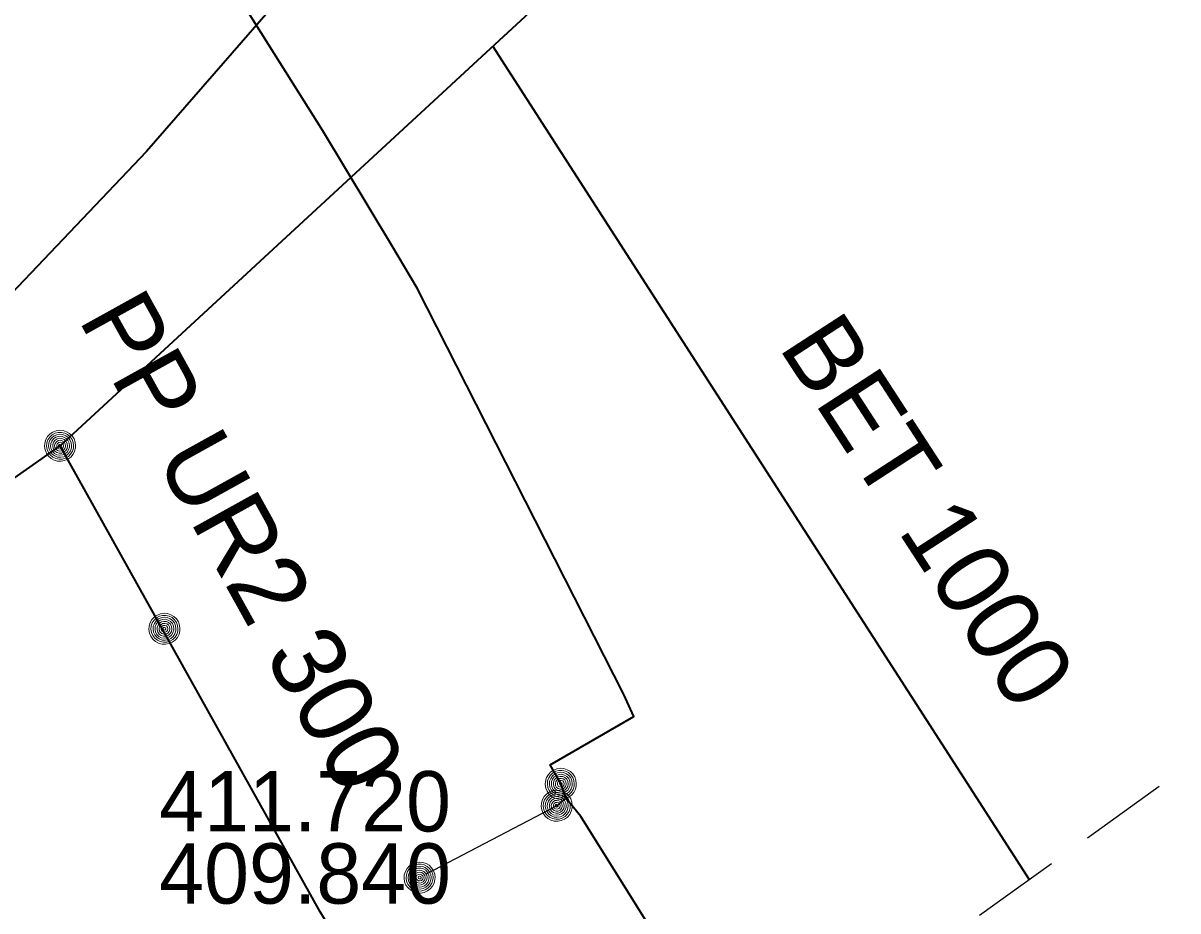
# Model space of a CAD drawing. Extents: x -867104 to -866746, y -1014489 to -1014255.
# Drawn here: x -866882.96 to -866865.74, y -1014478.06 to -1014464.82 of the extents above; entities that cross this region are included whole.
import ezdxf

# ---------------------------------------------------------------- set-up
doc = ezdxf.new("R2010")
doc.units = 0
doc.header["$LTSCALE"] = 0.44
doc.linetypes.add('DOT_DASHED', pattern=[7.7, 5, -1.2, 0.3, -1.2])
doc.linetypes.add('MEDIUM_DASHED', pattern=[4.5, 3, -1.5])
for name, color, linetype, lineweight in [('1', 7, 'Continuous', 35), ('12', 7, 'Continuous', 13), ('21', 7, 'Continuous', 35), ('25', 7, 'Continuous', 13), ('32', 7, 'Continuous', 13), ('62', 7, 'MEDIUM_DASHED', 25), ('8', 7, 'Continuous', 13)]:
    doc.layers.add(name, color=color, linetype=linetype, lineweight=lineweight)

msp = doc.modelspace()

# ---------------------------------------------------------------- linework, layer by layer
at = {"layer": '1'}
for points in [[(-866840.01, -1014396.11), (-866844.69, -1014400.78), (-866847.06, -1014402.96), (-866848.88, -1014406.15), (-866860.28, -1014424.67), (-866871.77, -1014440.29), (-866875.11, -1014444.27), (-866876.93, -1014446.09), (-866879, -1014449.37), (-866879.17, -1014450.73), (-866879.17, -1014451.68), (-866879.03, -1014452.53), (-866876.52, -1014455.41), (-866874.72, -1014458.69), (-866874.8, -1014459.33), (-866875.66, -1014460.47), (-866876.85, -1014461.77), (-866877.992, -1014463.135), (-866881.12, -1014466.73), (-866885.53, -1014471.37), (-866892.467, -1014476.423)], [(-866872.103, -1014480.579), (-866873.16, -1014479.02), (-866874.64, -1014476.65), (-866874.86, -1014476.38), (-866874.94, -1014476.16), (-866875.02, -1014476.02), (-866875.1, -1014475.88), (-866873.85, -1014475.16), (-866874, -1014474.83), (-866877.08, -1014468.77), (-866877.461, -1014468.135), (-866878.488, -1014466.421), (-866879.853, -1014464.243)]]:
    msp.add_lwpolyline(points, dxfattribs=at)
at = {"layer": '1', "linetype": 'DOT_DASHED', "lineweight": 25}
msp.add_lwpolyline([(-866874.86, -1014476.38), (-866875, -1014476.49), (-866877.045, -1014477.561)], dxfattribs=at)
at = {"layer": '12'}
for points in [[(-866874.708, -1014476.162), (-866874.714, -1014476.11), (-866874.731, -1014476.06), (-866874.76, -1014476.016), (-866874.797, -1014475.979), (-866874.842, -1014475.952), (-866874.892, -1014475.935), (-866874.945, -1014475.931), (-866874.997, -1014475.938), (-866875.046, -1014475.957), (-866875.089, -1014475.986), (-866875.125, -1014476.025), (-866875.151, -1014476.07), (-866875.167, -1014476.121), (-866875.17, -1014476.173), (-866875.162, -1014476.225), (-866875.142, -1014476.274), (-866875.111, -1014476.317), (-866875.072, -1014476.351), (-866875.026, -1014476.377), (-866874.975, -1014476.391), (-866874.922, -1014476.393), (-866874.871, -1014476.383), (-866874.823, -1014476.362), (-866874.78, -1014476.331), (-866874.746, -1014476.29), (-866874.722, -1014476.244), (-866874.71, -1014476.193)], [(-866874.738, -1014476.162), (-866874.744, -1014476.113), (-866874.761, -1014476.067), (-866874.789, -1014476.027), (-866874.826, -1014475.995), (-866874.87, -1014475.973), (-866874.918, -1014475.962), (-866874.967, -1014475.962), (-866875.014, -1014475.975), (-866875.057, -1014475.999), (-866875.093, -1014476.032), (-866875.12, -1014476.073), (-866875.136, -1014476.12), (-866875.14, -1014476.169), (-866875.133, -1014476.217), (-866875.114, -1014476.262), (-866875.084, -1014476.302), (-866875.046, -1014476.333), (-866875.002, -1014476.353), (-866874.954, -1014476.363), (-866874.905, -1014476.361), (-866874.858, -1014476.346), (-866874.815, -1014476.321), (-866874.781, -1014476.287), (-866874.755, -1014476.245), (-866874.741, -1014476.198)], [(-866874.768, -1014476.162), (-866874.774, -1014476.117), (-866874.791, -1014476.075), (-866874.819, -1014476.04), (-866874.855, -1014476.013), (-866874.897, -1014475.996), (-866874.942, -1014475.991), (-866874.987, -1014475.997), (-866875.028, -1014476.016), (-866875.063, -1014476.044), (-866875.09, -1014476.081), (-866875.106, -1014476.123), (-866875.11, -1014476.168), (-866875.103, -1014476.213), (-866875.084, -1014476.254), (-866875.055, -1014476.288), (-866875.018, -1014476.314), (-866874.975, -1014476.33), (-866874.93, -1014476.333), (-866874.885, -1014476.325), (-866874.845, -1014476.305), (-866874.811, -1014476.276), (-866874.785, -1014476.238), (-866874.771, -1014476.195)], [(-866874.798, -1014476.162), (-866874.803, -1014476.121), (-866874.821, -1014476.084), (-866874.848, -1014476.053), (-866874.883, -1014476.032), (-866874.923, -1014476.021), (-866874.964, -1014476.023), (-866875.003, -1014476.036), (-866875.037, -1014476.06), (-866875.062, -1014476.092), (-866875.077, -1014476.13), (-866875.08, -1014476.171), (-866875.072, -1014476.211), (-866875.052, -1014476.247), (-866875.023, -1014476.276), (-866874.986, -1014476.295), (-866874.946, -1014476.303), (-866874.905, -1014476.299), (-866874.867, -1014476.284), (-866874.835, -1014476.258), (-866874.812, -1014476.224), (-866874.799, -1014476.185)], [(-866874.828, -1014476.162), (-866874.833, -1014476.126), (-866874.851, -1014476.094), (-866874.877, -1014476.069), (-866874.911, -1014476.054), (-866874.947, -1014476.051), (-866874.982, -1014476.059), (-866875.013, -1014476.079), (-866875.036, -1014476.107), (-866875.049, -1014476.141), (-866875.049, -1014476.178), (-866875.038, -1014476.213), (-866875.017, -1014476.242), (-866874.987, -1014476.263), (-866874.952, -1014476.273), (-866874.915, -1014476.271), (-866874.881, -1014476.257), (-866874.854, -1014476.234), (-866874.835, -1014476.202), (-866874.828, -1014476.167)], [(-866874.858, -1014476.162), (-866874.863, -1014476.131), (-866874.88, -1014476.105), (-866874.906, -1014476.088), (-866874.936, -1014476.081), (-866874.967, -1014476.085), (-866874.994, -1014476.102), (-866875.012, -1014476.126), (-866875.02, -1014476.157), (-866875.016, -1014476.187), (-866875.001, -1014476.215), (-866874.977, -1014476.234), (-866874.947, -1014476.243), (-866874.916, -1014476.24), (-866874.888, -1014476.226), (-866874.868, -1014476.202), (-866874.858, -1014476.173)], [(-866874.888, -1014476.162), (-866874.893, -1014476.138), (-866874.91, -1014476.12), (-866874.933, -1014476.111), (-866874.957, -1014476.114), (-866874.978, -1014476.128), (-866874.989, -1014476.15), (-866874.989, -1014476.175), (-866874.977, -1014476.196), (-866874.957, -1014476.21), (-866874.932, -1014476.213), (-866874.909, -1014476.204), (-866874.893, -1014476.186)], [(-866874.918, -1014476.162), (-866874.923, -1014476.147), (-866874.938, -1014476.141), (-866874.953, -1014476.145), (-866874.96, -1014476.159), (-866874.956, -1014476.174), (-866874.943, -1014476.183), (-866874.928, -1014476.18), (-866874.918, -1014476.168)], [(-866874.769, -1014476.49), (-866874.775, -1014476.438), (-866874.792, -1014476.388), (-866874.821, -1014476.344), (-866874.858, -1014476.307), (-866874.903, -1014476.28), (-866874.953, -1014476.263), (-866875.006, -1014476.259), (-866875.058, -1014476.266), (-866875.107, -1014476.285), (-866875.15, -1014476.314), (-866875.186, -1014476.353), (-866875.212, -1014476.398), (-866875.228, -1014476.449), (-866875.231, -1014476.501), (-866875.223, -1014476.553), (-866875.203, -1014476.602), (-866875.172, -1014476.645), (-866875.133, -1014476.679), (-866875.087, -1014476.705), (-866875.036, -1014476.719), (-866874.983, -1014476.721), (-866874.932, -1014476.711), (-866874.884, -1014476.69), (-866874.841, -1014476.659), (-866874.807, -1014476.618), (-866874.783, -1014476.572), (-866874.771, -1014476.521)], [(-866874.799, -1014476.49), (-866874.805, -1014476.441), (-866874.822, -1014476.395), (-866874.85, -1014476.355), (-866874.887, -1014476.323), (-866874.931, -1014476.301), (-866874.979, -1014476.29), (-866875.028, -1014476.29), (-866875.075, -1014476.303), (-866875.118, -1014476.327), (-866875.154, -1014476.36), (-866875.181, -1014476.401), (-866875.197, -1014476.448), (-866875.201, -1014476.497), (-866875.194, -1014476.545), (-866875.175, -1014476.59), (-866875.145, -1014476.63), (-866875.107, -1014476.661), (-866875.063, -1014476.681), (-866875.015, -1014476.691), (-866874.966, -1014476.689), (-866874.919, -1014476.674), (-866874.876, -1014476.649), (-866874.842, -1014476.615), (-866874.816, -1014476.573), (-866874.802, -1014476.526)], [(-866874.829, -1014476.49), (-866874.835, -1014476.445), (-866874.852, -1014476.403), (-866874.88, -1014476.368), (-866874.916, -1014476.341), (-866874.958, -1014476.324), (-866875.003, -1014476.319), (-866875.048, -1014476.325), (-866875.089, -1014476.344), (-866875.124, -1014476.372), (-866875.151, -1014476.409), (-866875.167, -1014476.451), (-866875.171, -1014476.496), (-866875.164, -1014476.541), (-866875.145, -1014476.582), (-866875.116, -1014476.616), (-866875.079, -1014476.642), (-866875.036, -1014476.658), (-866874.991, -1014476.661), (-866874.946, -1014476.653), (-866874.906, -1014476.633), (-866874.872, -1014476.604), (-866874.846, -1014476.566), (-866874.832, -1014476.523)], [(-866874.859, -1014476.49), (-866874.864, -1014476.449), (-866874.882, -1014476.412), (-866874.909, -1014476.381), (-866874.944, -1014476.36), (-866874.984, -1014476.349), (-866875.025, -1014476.351), (-866875.064, -1014476.364), (-866875.098, -1014476.388), (-866875.123, -1014476.42), (-866875.138, -1014476.458), (-866875.141, -1014476.499), (-866875.133, -1014476.539), (-866875.113, -1014476.575), (-866875.084, -1014476.604), (-866875.047, -1014476.623), (-866875.007, -1014476.631), (-866874.966, -1014476.627), (-866874.928, -1014476.612), (-866874.896, -1014476.586), (-866874.873, -1014476.552), (-866874.86, -1014476.513)], [(-866874.889, -1014476.49), (-866874.894, -1014476.454), (-866874.912, -1014476.422), (-866874.938, -1014476.397), (-866874.972, -1014476.382), (-866875.008, -1014476.379), (-866875.043, -1014476.387), (-866875.074, -1014476.407), (-866875.097, -1014476.435), (-866875.11, -1014476.469), (-866875.11, -1014476.506), (-866875.099, -1014476.541), (-866875.078, -1014476.57), (-866875.048, -1014476.591), (-866875.013, -1014476.601), (-866874.976, -1014476.599), (-866874.942, -1014476.585), (-866874.915, -1014476.562), (-866874.896, -1014476.53), (-866874.889, -1014476.495)], [(-866874.919, -1014476.49), (-866874.924, -1014476.459), (-866874.941, -1014476.433), (-866874.967, -1014476.416), (-866874.997, -1014476.409), (-866875.028, -1014476.413), (-866875.055, -1014476.43), (-866875.073, -1014476.454), (-866875.081, -1014476.485), (-866875.077, -1014476.515), (-866875.062, -1014476.543), (-866875.038, -1014476.562), (-866875.008, -1014476.571), (-866874.977, -1014476.568), (-866874.949, -1014476.554), (-866874.929, -1014476.53), (-866874.919, -1014476.501)], [(-866874.949, -1014476.49), (-866874.954, -1014476.466), (-866874.971, -1014476.448), (-866874.994, -1014476.439), (-866875.018, -1014476.442), (-866875.039, -1014476.456), (-866875.05, -1014476.478), (-866875.05, -1014476.503), (-866875.038, -1014476.524), (-866875.018, -1014476.538), (-866874.993, -1014476.541), (-866874.97, -1014476.532), (-866874.954, -1014476.514)], [(-866874.979, -1014476.49), (-866874.984, -1014476.475), (-866874.999, -1014476.469), (-866875.014, -1014476.473), (-866875.021, -1014476.487), (-866875.017, -1014476.502), (-866875.004, -1014476.511), (-866874.989, -1014476.508), (-866874.979, -1014476.496)]]:
    msp.add_lwpolyline(points, close=True, dxfattribs=at)
at = {"layer": '21'}
for p, q in [((-866882.407, -1014471.12), (-866867.31, -1014457.18)), ((-866867.951, -1014477.595), (-866875.951, -1014465.158)), ((-866895.633, -1014480.423), (-866882.407, -1014471.12))]:
    msp.add_line(p, q, dxfattribs=at)
msp.add_lwpolyline([(-866877.78, -1014479.29), (-866878.53, -1014478.07), (-866882.407, -1014471.12)], dxfattribs=at)
at = {"layer": '25'}
for points in [[(-866880.619, -1014473.85), (-866880.625, -1014473.798), (-866880.642, -1014473.748), (-866880.671, -1014473.704), (-866880.708, -1014473.667), (-866880.753, -1014473.64), (-866880.803, -1014473.623), (-866880.856, -1014473.619), (-866880.907, -1014473.626), (-866880.956, -1014473.645), (-866881, -1014473.674), (-866881.036, -1014473.713), (-866881.062, -1014473.758), (-866881.078, -1014473.809), (-866881.081, -1014473.861), (-866881.073, -1014473.913), (-866881.053, -1014473.962), (-866881.022, -1014474.005), (-866880.983, -1014474.039), (-866880.937, -1014474.065), (-866880.886, -1014474.079), (-866880.833, -1014474.081), (-866880.782, -1014474.071), (-866880.733, -1014474.05), (-866880.691, -1014474.019), (-866880.657, -1014473.978), (-866880.633, -1014473.932), (-866880.62, -1014473.881)], [(-866880.649, -1014473.85), (-866880.655, -1014473.801), (-866880.672, -1014473.755), (-866880.7, -1014473.715), (-866880.737, -1014473.683), (-866880.781, -1014473.661), (-866880.829, -1014473.65), (-866880.878, -1014473.65), (-866880.924, -1014473.663), (-866880.968, -1014473.687), (-866881.004, -1014473.72), (-866881.031, -1014473.761), (-866881.047, -1014473.808), (-866881.051, -1014473.857), (-866881.044, -1014473.905), (-866881.025, -1014473.95), (-866880.995, -1014473.99), (-866880.956, -1014474.021), (-866880.913, -1014474.041), (-866880.865, -1014474.051), (-866880.816, -1014474.049), (-866880.769, -1014474.034), (-866880.726, -1014474.009), (-866880.691, -1014473.975), (-866880.666, -1014473.933), (-866880.652, -1014473.886)], [(-866880.679, -1014473.85), (-866880.684, -1014473.805), (-866880.701, -1014473.763), (-866880.73, -1014473.728), (-866880.766, -1014473.701), (-866880.808, -1014473.684), (-866880.853, -1014473.679), (-866880.897, -1014473.685), (-866880.939, -1014473.704), (-866880.973, -1014473.732), (-866881, -1014473.769), (-866881.017, -1014473.811), (-866881.021, -1014473.856), (-866881.014, -1014473.901), (-866880.995, -1014473.942), (-866880.966, -1014473.976), (-866880.929, -1014474.002), (-866880.886, -1014474.018), (-866880.841, -1014474.021), (-866880.796, -1014474.013), (-866880.755, -1014473.993), (-866880.722, -1014473.964), (-866880.696, -1014473.926), (-866880.682, -1014473.883)], [(-866880.709, -1014473.85), (-866880.713, -1014473.809), (-866880.732, -1014473.772), (-866880.759, -1014473.741), (-866880.794, -1014473.72), (-866880.834, -1014473.709), (-866880.875, -1014473.711), (-866880.914, -1014473.724), (-866880.948, -1014473.748), (-866880.973, -1014473.78), (-866880.988, -1014473.818), (-866880.99, -1014473.859), (-866880.983, -1014473.899), (-866880.963, -1014473.935), (-866880.934, -1014473.964), (-866880.897, -1014473.983), (-866880.857, -1014473.991), (-866880.816, -1014473.987), (-866880.777, -1014473.972), (-866880.745, -1014473.946), (-866880.723, -1014473.912), (-866880.71, -1014473.873)], [(-866880.739, -1014473.85), (-866880.744, -1014473.814), (-866880.762, -1014473.782), (-866880.788, -1014473.757), (-866880.821, -1014473.742), (-866880.858, -1014473.739), (-866880.892, -1014473.747), (-866880.924, -1014473.767), (-866880.946, -1014473.795), (-866880.96, -1014473.829), (-866880.96, -1014473.866), (-866880.949, -1014473.901), (-866880.928, -1014473.93), (-866880.897, -1014473.951), (-866880.863, -1014473.961), (-866880.826, -1014473.959), (-866880.792, -1014473.945), (-866880.765, -1014473.922), (-866880.745, -1014473.89), (-866880.739, -1014473.855)], [(-866880.769, -1014473.85), (-866880.774, -1014473.819), (-866880.791, -1014473.793), (-866880.816, -1014473.776), (-866880.847, -1014473.769), (-866880.878, -1014473.773), (-866880.905, -1014473.79), (-866880.923, -1014473.814), (-866880.931, -1014473.845), (-866880.927, -1014473.875), (-866880.912, -1014473.903), (-866880.887, -1014473.922), (-866880.858, -1014473.931), (-866880.826, -1014473.928), (-866880.799, -1014473.914), (-866880.779, -1014473.89), (-866880.769, -1014473.861)], [(-866880.799, -1014473.85), (-866880.804, -1014473.826), (-866880.821, -1014473.808), (-866880.843, -1014473.799), (-866880.868, -1014473.802), (-866880.889, -1014473.816), (-866880.9, -1014473.838), (-866880.9, -1014473.863), (-866880.887, -1014473.884), (-866880.868, -1014473.898), (-866880.843, -1014473.901), (-866880.82, -1014473.892), (-866880.804, -1014473.874)], [(-866880.829, -1014473.85), (-866880.834, -1014473.835), (-866880.848, -1014473.829), (-866880.864, -1014473.833), (-866880.87, -1014473.847), (-866880.867, -1014473.862), (-866880.853, -1014473.871), (-866880.838, -1014473.868), (-866880.829, -1014473.856)]]:
    msp.add_lwpolyline(points, close=True, dxfattribs=at)
at = {"layer": '32'}
for points in [[(-866882.176, -1014471.12), (-866882.182, -1014471.068), (-866882.199, -1014471.018), (-866882.228, -1014470.974), (-866882.265, -1014470.937), (-866882.31, -1014470.91), (-866882.36, -1014470.893), (-866882.413, -1014470.889), (-866882.465, -1014470.896), (-866882.514, -1014470.915), (-866882.557, -1014470.944), (-866882.593, -1014470.983), (-866882.619, -1014471.028), (-866882.635, -1014471.079), (-866882.638, -1014471.131), (-866882.63, -1014471.183), (-866882.61, -1014471.232), (-866882.579, -1014471.275), (-866882.54, -1014471.309), (-866882.494, -1014471.335), (-866882.443, -1014471.349), (-866882.39, -1014471.351), (-866882.339, -1014471.341), (-866882.291, -1014471.32), (-866882.248, -1014471.289), (-866882.214, -1014471.248), (-866882.19, -1014471.202), (-866882.178, -1014471.151)], [(-866882.206, -1014471.12), (-866882.212, -1014471.071), (-866882.229, -1014471.025), (-866882.257, -1014470.985), (-866882.294, -1014470.953), (-866882.338, -1014470.931), (-866882.386, -1014470.92), (-866882.435, -1014470.92), (-866882.482, -1014470.933), (-866882.525, -1014470.957), (-866882.561, -1014470.99), (-866882.588, -1014471.031), (-866882.604, -1014471.078), (-866882.608, -1014471.127), (-866882.601, -1014471.175), (-866882.582, -1014471.22), (-866882.552, -1014471.26), (-866882.514, -1014471.291), (-866882.47, -1014471.311), (-866882.422, -1014471.321), (-866882.373, -1014471.319), (-866882.326, -1014471.304), (-866882.283, -1014471.279), (-866882.249, -1014471.245), (-866882.223, -1014471.203), (-866882.209, -1014471.156)], [(-866882.236, -1014471.12), (-866882.242, -1014471.075), (-866882.259, -1014471.033), (-866882.287, -1014470.998), (-866882.323, -1014470.971), (-866882.365, -1014470.954), (-866882.41, -1014470.949), (-866882.455, -1014470.955), (-866882.496, -1014470.974), (-866882.531, -1014471.002), (-866882.558, -1014471.039), (-866882.574, -1014471.081), (-866882.578, -1014471.126), (-866882.571, -1014471.171), (-866882.552, -1014471.212), (-866882.523, -1014471.246), (-866882.486, -1014471.272), (-866882.443, -1014471.288), (-866882.398, -1014471.291), (-866882.353, -1014471.283), (-866882.313, -1014471.263), (-866882.279, -1014471.234), (-866882.253, -1014471.196), (-866882.239, -1014471.153)], [(-866882.266, -1014471.12), (-866882.271, -1014471.079), (-866882.289, -1014471.042), (-866882.316, -1014471.011), (-866882.351, -1014470.99), (-866882.391, -1014470.979), (-866882.432, -1014470.981), (-866882.471, -1014470.994), (-866882.505, -1014471.018), (-866882.53, -1014471.05), (-866882.545, -1014471.088), (-866882.548, -1014471.129), (-866882.54, -1014471.169), (-866882.52, -1014471.205), (-866882.491, -1014471.234), (-866882.454, -1014471.253), (-866882.414, -1014471.261), (-866882.373, -1014471.257), (-866882.335, -1014471.242), (-866882.303, -1014471.216), (-866882.28, -1014471.182), (-866882.267, -1014471.143)], [(-866882.296, -1014471.12), (-866882.301, -1014471.084), (-866882.319, -1014471.052), (-866882.345, -1014471.027), (-866882.379, -1014471.012), (-866882.415, -1014471.009), (-866882.45, -1014471.017), (-866882.481, -1014471.037), (-866882.504, -1014471.065), (-866882.517, -1014471.099), (-866882.517, -1014471.136), (-866882.506, -1014471.171), (-866882.485, -1014471.2), (-866882.455, -1014471.221), (-866882.42, -1014471.231), (-866882.383, -1014471.229), (-866882.349, -1014471.215), (-866882.322, -1014471.192), (-866882.303, -1014471.16), (-866882.296, -1014471.125)], [(-866882.326, -1014471.12), (-866882.331, -1014471.089), (-866882.348, -1014471.063), (-866882.374, -1014471.046), (-866882.404, -1014471.039), (-866882.435, -1014471.043), (-866882.462, -1014471.06), (-866882.48, -1014471.084), (-866882.488, -1014471.115), (-866882.484, -1014471.145), (-866882.469, -1014471.173), (-866882.445, -1014471.192), (-866882.415, -1014471.201), (-866882.384, -1014471.198), (-866882.356, -1014471.184), (-866882.336, -1014471.16), (-866882.326, -1014471.131)], [(-866882.356, -1014471.12), (-866882.361, -1014471.096), (-866882.378, -1014471.078), (-866882.401, -1014471.069), (-866882.425, -1014471.072), (-866882.446, -1014471.086), (-866882.457, -1014471.108), (-866882.457, -1014471.133), (-866882.445, -1014471.154), (-866882.425, -1014471.168), (-866882.4, -1014471.171), (-866882.377, -1014471.162), (-866882.361, -1014471.144)], [(-866882.386, -1014471.12), (-866882.391, -1014471.105), (-866882.406, -1014471.099), (-866882.421, -1014471.103), (-866882.428, -1014471.117), (-866882.424, -1014471.132), (-866882.411, -1014471.141), (-866882.396, -1014471.138), (-866882.386, -1014471.126)]]:
    msp.add_lwpolyline(points, close=True, dxfattribs=at)
at = {"layer": '62'}
msp.add_lwpolyline([(-867100.742, -1014391.242), (-867092.704, -1014271.063), (-867058.137, -1014262.221), (-866832.652, -1014254.584), (-866798.889, -1014276.691), (-866769.95, -1014301.209), (-866746.236, -1014362.705), (-866806.526, -1014433.445), (-866883.697, -1014488.912), (-866958.859, -1014435.455)], close=True, dxfattribs=at)
at = {"layer": '8'}
for points in [[(-866876.814, -1014477.561), (-866876.82, -1014477.509), (-866876.837, -1014477.459), (-866876.866, -1014477.415), (-866876.903, -1014477.378), (-866876.948, -1014477.351), (-866876.998, -1014477.334), (-866877.051, -1014477.33), (-866877.103, -1014477.337), (-866877.152, -1014477.356), (-866877.195, -1014477.385), (-866877.231, -1014477.424), (-866877.257, -1014477.469), (-866877.273, -1014477.52), (-866877.276, -1014477.572), (-866877.268, -1014477.624), (-866877.248, -1014477.673), (-866877.217, -1014477.716), (-866877.178, -1014477.75), (-866877.132, -1014477.776), (-866877.081, -1014477.79), (-866877.028, -1014477.792), (-866876.977, -1014477.782), (-866876.929, -1014477.761), (-866876.886, -1014477.73), (-866876.852, -1014477.689), (-866876.828, -1014477.643), (-866876.816, -1014477.592)], [(-866876.844, -1014477.561), (-866876.85, -1014477.512), (-866876.867, -1014477.466), (-866876.895, -1014477.426), (-866876.932, -1014477.394), (-866876.976, -1014477.372), (-866877.024, -1014477.361), (-866877.073, -1014477.361), (-866877.12, -1014477.374), (-866877.163, -1014477.398), (-866877.199, -1014477.431), (-866877.226, -1014477.472), (-866877.242, -1014477.519), (-866877.246, -1014477.568), (-866877.239, -1014477.616), (-866877.22, -1014477.661), (-866877.19, -1014477.701), (-866877.152, -1014477.732), (-866877.108, -1014477.752), (-866877.06, -1014477.762), (-866877.011, -1014477.76), (-866876.964, -1014477.745), (-866876.921, -1014477.72), (-866876.887, -1014477.686), (-866876.861, -1014477.644), (-866876.847, -1014477.597)], [(-866876.874, -1014477.561), (-866876.88, -1014477.516), (-866876.897, -1014477.474), (-866876.925, -1014477.439), (-866876.961, -1014477.412), (-866877.003, -1014477.395), (-866877.048, -1014477.39), (-866877.093, -1014477.396), (-866877.134, -1014477.415), (-866877.169, -1014477.443), (-866877.196, -1014477.48), (-866877.212, -1014477.522), (-866877.216, -1014477.567), (-866877.209, -1014477.612), (-866877.19, -1014477.653), (-866877.161, -1014477.687), (-866877.124, -1014477.713), (-866877.081, -1014477.729), (-866877.036, -1014477.732), (-866876.991, -1014477.724), (-866876.951, -1014477.704), (-866876.917, -1014477.675), (-866876.891, -1014477.637), (-866876.877, -1014477.594)], [(-866876.904, -1014477.561), (-866876.909, -1014477.52), (-866876.927, -1014477.483), (-866876.954, -1014477.452), (-866876.989, -1014477.431), (-866877.029, -1014477.42), (-866877.07, -1014477.422), (-866877.109, -1014477.435), (-866877.143, -1014477.459), (-866877.168, -1014477.491), (-866877.183, -1014477.529), (-866877.186, -1014477.57), (-866877.178, -1014477.61), (-866877.158, -1014477.646), (-866877.129, -1014477.675), (-866877.092, -1014477.694), (-866877.052, -1014477.702), (-866877.011, -1014477.698), (-866876.973, -1014477.683), (-866876.941, -1014477.657), (-866876.918, -1014477.623), (-866876.905, -1014477.584)], [(-866876.934, -1014477.561), (-866876.939, -1014477.525), (-866876.957, -1014477.493), (-866876.983, -1014477.468), (-866877.017, -1014477.453), (-866877.053, -1014477.45), (-866877.088, -1014477.458), (-866877.119, -1014477.478), (-866877.142, -1014477.506), (-866877.155, -1014477.54), (-866877.155, -1014477.577), (-866877.144, -1014477.612), (-866877.123, -1014477.641), (-866877.093, -1014477.662), (-866877.058, -1014477.672), (-866877.021, -1014477.67), (-866876.987, -1014477.656), (-866876.96, -1014477.633), (-866876.941, -1014477.601), (-866876.934, -1014477.566)], [(-866876.964, -1014477.561), (-866876.969, -1014477.53), (-866876.986, -1014477.504), (-866877.012, -1014477.487), (-866877.042, -1014477.48), (-866877.073, -1014477.484), (-866877.1, -1014477.501), (-866877.118, -1014477.525), (-866877.126, -1014477.556), (-866877.122, -1014477.586), (-866877.107, -1014477.614), (-866877.083, -1014477.633), (-866877.053, -1014477.642), (-866877.022, -1014477.639), (-866876.994, -1014477.625), (-866876.974, -1014477.601), (-866876.964, -1014477.572)], [(-866876.994, -1014477.561), (-866876.999, -1014477.537), (-866877.016, -1014477.519), (-866877.039, -1014477.51), (-866877.063, -1014477.513), (-866877.084, -1014477.527), (-866877.095, -1014477.549), (-866877.095, -1014477.574), (-866877.083, -1014477.595), (-866877.063, -1014477.609), (-866877.038, -1014477.612), (-866877.015, -1014477.603), (-866876.999, -1014477.585)], [(-866877.024, -1014477.561), (-866877.029, -1014477.546), (-866877.044, -1014477.54), (-866877.059, -1014477.544), (-866877.066, -1014477.558), (-866877.062, -1014477.573), (-866877.049, -1014477.582), (-866877.034, -1014477.579), (-866877.024, -1014477.567)]]:
    msp.add_lwpolyline(points, close=True, dxfattribs=at)

# ---------------------------------------------------------------- texts
at = {"layer": '1'}
for s, rotation, p in [('PP UR2 300', 299, (-866882.144, -1014469.231)), ('BET 1000', 303, (-866871.703, -1014469.645))]:
    msp.add_text(s, height=1.1, rotation=rotation, dxfattribs=at).set_placement(p)
for s, p in [('411.720 ', (-866880.928, -1014476.873)), ('409.840 ', (-866880.928, -1014477.95))]:
    msp.add_text(s, height=0.9, dxfattribs=at).set_placement(p)

doc.saveas('drawing.dxf')
